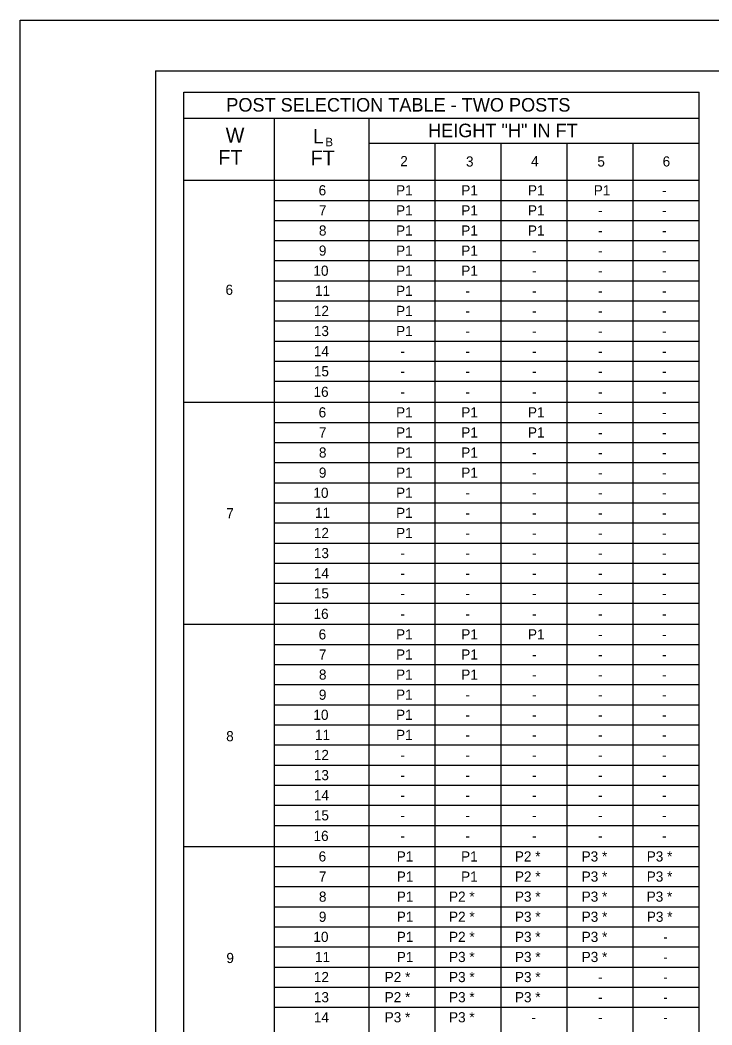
# Model space of a CAD drawing. Extents: x -2340 to 628, y -879 to 309.
# Drawn here: x -1117.4 to -912.9, y -581.5 to -284.6 of the extents above; entities that cross this region are included whole.
import ezdxf

# ---------------------------------------------------------------- set-up
doc = ezdxf.new("R2010")
doc.units = 0
for name, color, linetype in [('Level 1', 7, 'Continuous'), ('Level 2', 7, 'Continuous'), ('Level 30', 7, 'Continuous'), ('PLT-BNDY', 7, 'Continuous')]:
    doc.layers.add(name, color=color, linetype=linetype)

msp = doc.modelspace()

# ---------------------------------------------------------------- linework, layer by layer
at = {"layer": 'Level 1'}
for p, q in [((-1077.39, -299.56), (-291.39, -299.56)), ((-1077.39, -299.56), (-1077.39, -863.56)), ((-1069, -331.88), (-1069, -305.86)), ((-1069, -305.86), (-916.65, -305.86)), ((-916.65, -331.88), (-916.65, -305.86)), ((-1069, -313.54), (-916.65, -313.54)), ((-1042.2, -331.88), (-1042.2, -313.54)), ((-1014.19, -331.88), (-1014.19, -313.54)), ((-994.68, -331.88), (-994.68, -320.88)), ((-975.17, -331.88), (-975.17, -320.88)), ((-955.67, -331.88), (-955.67, -320.88)), ((-936.16, -331.88), (-936.16, -320.88)), ((-1069, -856.76), (-1069, -331.88)), ((-1069, -331.88), (-916.65, -331.88)), ((-975.85, -331.88), (-940.21, -331.88)), ((-916.65, -856.76), (-916.65, -331.88)), ((-975.85, -528.71), (-940.21, -528.71)), ((-940.21, -528.71), (-916.65, -528.71))]:
    msp.add_line(p, q, dxfattribs=at)
at = {"layer": 'Level 2'}
for p, q in [((-1014.19, -320.88), (-916.65, -320.88)), ((-1042.2, -856.76), (-1042.2, -331.88)), ((-1014.19, -856.76), (-1014.19, -331.88)), ((-994.68, -856.76), (-994.68, -331.88)), ((-975.17, -856.76), (-975.17, -331.88)), ((-955.67, -856.76), (-955.67, -331.88)), ((-936.16, -856.76), (-936.16, -331.88)), ((-1042.2, -337.82), (-916.65, -337.82)), ((-975.85, -337.82), (-940.21, -337.82)), ((-940.21, -337.82), (-916.65, -337.82)), ((-1042.2, -343.76), (-916.65, -343.76)), ((-975.85, -343.76), (-940.21, -343.76)), ((-940.21, -343.76), (-916.65, -343.76)), ((-1042.2, -349.7), (-916.65, -349.7)), ((-975.85, -349.7), (-940.21, -349.7)), ((-940.21, -349.7), (-916.65, -349.7)), ((-1042.2, -355.64), (-916.65, -355.64)), ((-975.85, -355.64), (-940.21, -355.64)), ((-940.21, -355.64), (-916.65, -355.64)), ((-1042.2, -361.58), (-916.65, -361.58)), ((-975.85, -361.58), (-940.21, -361.58)), ((-940.21, -361.58), (-916.65, -361.58)), ((-1042.2, -367.52), (-916.65, -367.52)), ((-975.85, -367.52), (-940.21, -367.52)), ((-940.21, -367.52), (-916.65, -367.52)), ((-1042.2, -373.46), (-916.65, -373.46)), ((-975.85, -373.46), (-940.21, -373.46)), ((-940.21, -373.46), (-916.65, -373.46)), ((-1042.2, -379.4), (-916.65, -379.4)), ((-975.85, -379.4), (-940.21, -379.4)), ((-940.21, -379.4), (-916.65, -379.4)), ((-1042.2, -385.34), (-916.65, -385.34)), ((-975.85, -385.34), (-940.21, -385.34)), ((-940.21, -385.34), (-916.65, -385.34)), ((-1042.2, -391.28), (-916.65, -391.28)), ((-975.85, -391.28), (-940.21, -391.28)), ((-940.21, -391.28), (-916.65, -391.28)), ((-1069, -397.49), (-916.65, -397.49)), ((-975.85, -397.49), (-940.21, -397.49)), ((-940.21, -397.49), (-916.65, -397.49)), ((-1042.2, -403.43), (-916.65, -403.43)), ((-975.85, -403.43), (-940.21, -403.43)), ((-940.21, -403.43), (-916.65, -403.43)), ((-1042.2, -409.37), (-916.65, -409.37)), ((-975.85, -409.37), (-940.21, -409.37)), ((-940.21, -409.37), (-916.65, -409.37)), ((-1042.2, -415.31), (-916.65, -415.31)), ((-975.85, -415.31), (-940.21, -415.31)), ((-940.21, -415.31), (-916.65, -415.31)), ((-1042.2, -421.25), (-916.65, -421.25)), ((-975.85, -421.25), (-940.21, -421.25)), ((-940.21, -421.25), (-916.65, -421.25)), ((-1042.2, -427.19), (-916.65, -427.19)), ((-975.85, -427.19), (-940.21, -427.19)), ((-940.21, -427.19), (-916.65, -427.19)), ((-1042.2, -433.13), (-916.65, -433.13)), ((-975.85, -433.13), (-940.21, -433.13)), ((-940.21, -433.13), (-916.65, -433.13)), ((-1042.2, -439.07), (-916.65, -439.07)), ((-975.85, -439.07), (-940.21, -439.07)), ((-940.21, -439.07), (-916.65, -439.07)), ((-1042.2, -445.01), (-916.65, -445.01)), ((-975.85, -445.01), (-940.21, -445.01)), ((-940.21, -445.01), (-916.65, -445.01)), ((-1042.2, -450.95), (-916.65, -450.95)), ((-975.85, -450.95), (-940.21, -450.95)), ((-1042.2, -456.89), (-916.65, -456.89)), ((-975.85, -456.89), (-940.21, -456.89)), ((-1069, -463.1), (-916.65, -463.1)), ((-975.85, -463.1), (-940.21, -463.1)), ((-1042.2, -469.04), (-916.65, -469.04)), ((-975.85, -469.04), (-940.21, -469.04)), ((-1042.2, -474.98), (-916.65, -474.98)), ((-975.85, -474.98), (-940.21, -474.98)), ((-1042.2, -480.92), (-916.65, -480.92)), ((-975.85, -480.92), (-940.21, -480.92)), ((-1042.2, -486.86), (-916.65, -486.86)), ((-975.85, -486.86), (-940.21, -486.86)), ((-1042.2, -492.8), (-916.65, -492.8)), ((-975.85, -492.8), (-940.21, -492.8)), ((-1042.2, -498.74), (-916.65, -498.74)), ((-1042.2, -504.68), (-916.65, -504.68)), ((-1042.2, -510.62), (-916.65, -510.62)), ((-1042.2, -516.56), (-916.65, -516.56)), ((-1042.2, -522.5), (-916.65, -522.5)), ((-1069, -528.71), (-916.65, -528.71)), ((-1042.2, -534.65), (-916.65, -534.65)), ((-1042.2, -540.59), (-916.65, -540.59)), ((-1042.2, -546.53), (-916.65, -546.53)), ((-1042.2, -552.47), (-916.65, -552.47)), ((-1042.2, -558.41), (-916.65, -558.41)), ((-1042.2, -564.35), (-916.65, -564.35)), ((-1042.2, -570.29), (-916.65, -570.29)), ((-1042.2, -576.23), (-916.65, -576.23))]:
    msp.add_line(p, q, dxfattribs=at)
at = {"layer": 'PLT-BNDY'}
msp.add_lwpolyline([(-1117.39, -284.56), (-276.39, -284.56), (-276.39, -878.56), (-1117.39, -878.56)], close=True, dxfattribs=at)

# ---------------------------------------------------------------- texts
at = {"layer": 'Level 1'}
for s, height, p in [('POST SELECTION TABLE - TWO POSTS', 4.003, (-1056.42, -311.6)), ('W', 4.37, (-1056.6, -320.74)), ('L', 4.3, (-1030.81, -321.01)), ('HEIGHT "H" IN FT', 4.003, (-996.77, -319.17)), ('B', 2.5, (-1027.1, -321.84)), ('FT', 4.375, (-1058.77, -327.3)), ('FT', 4.375, (-1031.5, -327.47)), ('2', 3, (-1005, -327.74)), ('3', 3, (-985.57, -327.84)), ('4', 3, (-966.32, -327.74)), ('5', 3, (-946.73, -327.84)), ('6', 3, (-927.43, -327.82))]:
    msp.add_text(s, height=height, dxfattribs=at).set_placement(p)
at = {"layer": 'Level 2'}
for s, p in [('7', (-1029.04, -342.29)), ('P1', (-1006.23, -342.29)), ('P1', (-986.96, -342.29)), ('P1', (-967.25, -342.29)), ('-', (-946.52, -342.29)), ('-', (-927.58, -342.29)), ('8', (-1029.04, -348.23)), ('P1', (-1006.23, -348.23)), ('P1', (-986.96, -348.23)), ('P1', (-967.25, -348.23)), ('-', (-946.52, -348.23)), ('-', (-927.58, -348.23)), ('9', (-1029.06, -354.17)), ('P1', (-1006.23, -354.17)), ('P1', (-986.96, -354.17)), ('-', (-965.98, -354.17)), ('-', (-946.52, -354.17)), ('-', (-927.58, -354.17)), ('10', (-1030.67, -360.11)), ('P1', (-1006.23, -360.11)), ('P1', (-986.96, -360.11)), ('-', (-965.98, -360.11)), ('-', (-946.52, -360.11)), ('-', (-927.58, -360.11)), ('11', (-1030.2, -366.05)), ('P1', (-1006.23, -366.05)), ('-', (-985.69, -366.05)), ('-', (-965.98, -366.05)), ('-', (-946.52, -366.05)), ('-', (-927.58, -366.05)), ('12', (-1030.54, -371.99)), ('P1', (-1006.23, -371.99)), ('-', (-985.69, -371.99)), ('-', (-965.98, -371.99)), ('-', (-946.52, -371.99)), ('-', (-927.58, -371.99)), ('13', (-1030.54, -377.93)), ('P1', (-1006.23, -377.93)), ('-', (-985.69, -377.93)), ('-', (-965.98, -377.93)), ('-', (-946.52, -377.93)), ('-', (-927.58, -377.93)), ('14', (-1030.54, -383.87)), ('-', (-1004.95, -383.87)), ('-', (-985.69, -383.87)), ('-', (-965.98, -383.87)), ('-', (-946.52, -383.87)), ('-', (-927.58, -383.87)), ('15', (-1030.54, -389.81)), ('-', (-1004.95, -389.81)), ('-', (-985.69, -389.81)), ('-', (-965.98, -389.81)), ('-', (-946.52, -389.81)), ('-', (-927.58, -389.81)), ('16', (-1030.63, -395.89)), ('-', (-1004.95, -395.89)), ('-', (-985.69, -395.89)), ('-', (-965.98, -395.89)), ('-', (-946.52, -395.89)), ('-', (-927.58, -395.89)), ('P1', (-1006.23, -401.96)), ('P1', (-986.96, -401.96)), ('P1', (-967.25, -401.96)), ('-', (-946.52, -401.96)), ('-', (-927.58, -401.96)), ('7', (-1029.04, -407.9)), ('P1', (-1006.23, -407.9)), ('P1', (-986.96, -407.9)), ('P1', (-967.25, -407.9)), ('-', (-946.52, -407.9)), ('-', (-927.58, -407.9)), ('8', (-1029.04, -413.84)), ('P1', (-1006.23, -413.84)), ('P1', (-986.96, -413.84)), ('-', (-965.98, -413.84)), ('-', (-946.52, -413.84)), ('-', (-927.58, -413.84)), ('9', (-1029.06, -419.78)), ('P1', (-1006.23, -419.78)), ('P1', (-986.96, -419.78)), ('-', (-965.98, -419.78)), ('-', (-946.52, -419.78)), ('-', (-927.58, -419.78)), ('10', (-1030.67, -425.72)), ('P1', (-1006.23, -425.72)), ('-', (-985.69, -425.72)), ('-', (-965.98, -425.72)), ('-', (-946.52, -425.72)), ('-', (-927.58, -425.72)), ('7', (-1056.43, -431.77)), ('11', (-1030.2, -431.66)), ('P1', (-1006.23, -431.66)), ('-', (-985.69, -431.66)), ('-', (-965.98, -431.66)), ('-', (-946.52, -431.66)), ('-', (-927.58, -431.66)), ('12', (-1030.54, -437.6)), ('P1', (-1006.23, -437.6)), ('-', (-985.69, -437.6)), ('-', (-965.98, -437.6)), ('-', (-946.52, -437.6)), ('-', (-927.58, -437.6)), ('13', (-1030.54, -443.54)), ('-', (-1004.95, -443.54)), ('-', (-985.69, -443.54)), ('-', (-965.98, -443.54)), ('-', (-946.52, -443.54)), ('-', (-927.58, -443.54)), ('14', (-1030.54, -449.48)), ('-', (-1004.95, -449.48)), ('-', (-985.69, -449.48)), ('-', (-965.98, -449.48)), ('-', (-946.52, -449.48)), ('-', (-927.58, -449.48)), ('15', (-1030.54, -455.42)), ('-', (-1004.95, -455.42)), ('-', (-985.69, -455.42)), ('-', (-965.98, -455.42)), ('-', (-946.52, -455.42)), ('-', (-927.58, -455.42)), ('16', (-1030.63, -461.5)), ('-', (-1004.95, -461.5)), ('-', (-985.69, -461.5)), ('-', (-965.98, -461.5)), ('-', (-946.52, -461.5)), ('-', (-927.58, -461.5)), ('P1', (-1006.23, -467.57)), ('P1', (-986.96, -467.57)), ('P1', (-967.25, -467.57)), ('-', (-946.52, -467.57)), ('-', (-927.58, -467.57)), ('7', (-1029.04, -473.51)), ('P1', (-1006.23, -473.51)), ('P1', (-986.96, -473.51)), ('-', (-965.98, -473.51)), ('-', (-946.52, -473.51)), ('-', (-927.58, -473.51)), ('8', (-1029.04, -479.45)), ('P1', (-1006.23, -479.45)), ('P1', (-986.96, -479.45)), ('-', (-965.98, -479.45)), ('-', (-946.52, -479.45)), ('-', (-927.58, -479.45)), ('9', (-1029.06, -485.39)), ('P1', (-1006.23, -485.39)), ('-', (-985.69, -485.39)), ('-', (-965.98, -485.39)), ('-', (-946.52, -485.39)), ('-', (-927.58, -485.39)), ('10', (-1030.67, -491.33)), ('P1', (-1006.23, -491.33)), ('-', (-985.69, -491.33)), ('-', (-965.98, -491.33)), ('-', (-946.52, -491.33)), ('-', (-927.58, -491.33)), ('8', (-1056.46, -497.64)), ('11', (-1030.2, -497.27)), ('P1', (-1006.23, -497.27)), ('-', (-985.69, -497.27)), ('-', (-965.98, -497.27)), ('-', (-946.52, -497.27)), ('-', (-927.58, -497.27)), ('12', (-1030.54, -503.21)), ('-', (-1004.95, -503.21)), ('-', (-985.69, -503.21)), ('-', (-965.98, -503.21)), ('-', (-946.52, -503.21)), ('-', (-927.58, -503.21)), ('13', (-1030.54, -509.15)), ('-', (-1004.95, -509.15)), ('-', (-985.69, -509.15)), ('-', (-965.98, -509.15)), ('-', (-946.52, -509.15)), ('-', (-927.58, -509.15)), ('14', (-1030.54, -515.09)), ('-', (-1004.95, -515.09)), ('-', (-985.69, -515.09)), ('-', (-965.98, -515.09)), ('-', (-946.52, -515.09)), ('-', (-927.58, -515.09)), ('15', (-1030.54, -521.03)), ('-', (-1004.95, -521.03)), ('-', (-985.69, -521.03)), ('-', (-965.98, -521.03)), ('-', (-946.52, -521.03)), ('-', (-927.58, -521.03)), ('16', (-1030.63, -527.11)), ('-', (-1004.95, -527.11)), ('-', (-985.69, -527.11)), ('-', (-965.98, -527.11)), ('-', (-946.52, -527.11)), ('-', (-927.58, -527.11)), ('P1', (-1006.04, -533.18)), ('P1', (-987.01, -533.18)), ('P2 *', (-971.12, -533.18)), ('P3 *', (-951.38, -533.18)), ('P3 *', (-932.13, -533.18)), ('7', (-1029.04, -539.12)), ('P1', (-1006.02, -539.12)), ('P1', (-987.01, -539.12)), ('P2 *', (-971.1, -539.12)), ('P3 *', (-951.36, -539.12)), ('P3 *', (-932.13, -539.12)), ('8', (-1029.04, -545.06)), ('P1', (-1006.02, -545.06)), ('P2 *', (-990.58, -545.06)), ('P3 *', (-971.1, -545.06)), ('P3 *', (-951.36, -545.06)), ('P3 *', (-932.15, -545.06)), ('9', (-1029.06, -551)), ('P1', (-1006.02, -551)), ('P2 *', (-990.58, -551)), ('P3 *', (-971.1, -551)), ('P3 *', (-951.36, -551)), ('P3 *', (-932.1, -551)), ('10', (-1030.67, -556.94)), ('P1', (-1006.02, -556.94)), ('P2 *', (-990.58, -556.94)), ('P3 *', (-971.1, -556.94)), ('P3 *', (-951.36, -556.94)), ('-', (-927.25, -556.94)), ('9', (-1056.4, -563.18)), ('11', (-1030.2, -562.88)), ('P1', (-1006.02, -562.88)), ('P3 *', (-990.58, -562.88)), ('P3 *', (-971.1, -562.88)), ('P3 *', (-951.36, -562.88)), ('-', (-927.25, -562.88)), ('12', (-1030.54, -568.82)), ('P2 *', (-1009.6, -568.82)), ('P3 *', (-990.58, -568.82)), ('P3 *', (-971.1, -568.82)), ('-', (-946.51, -568.82)), ('-', (-927.25, -568.82)), ('13', (-1030.54, -574.76)), ('P2 *', (-1009.6, -574.76)), ('P3 *', (-990.58, -574.76)), ('P3 *', (-971.1, -574.76)), ('-', (-946.51, -574.76)), ('-', (-927.25, -574.76)), ('14', (-1030.54, -580.7)), ('P3 *', (-1009.6, -580.7)), ('P3 *', (-990.58, -580.7)), ('-', (-966.25, -580.7)), ('-', (-946.51, -580.7)), ('-', (-927.25, -580.7))]:
    msp.add_text(s, height=3, dxfattribs=at).set_placement(p)
at = {"layer": 'Level 30'}
for s, p in [('6', (-1029.13, -336.35)), ('P1', (-1006.23, -336.35)), ('P1', (-986.96, -336.35)), ('P1', (-967.25, -336.35)), ('P1', (-947.8, -336.35)), ('-', (-927.58, -336.35)), ('6', (-1056.66, -365.75)), ('6', (-1029.13, -401.96)), ('6', (-1029.13, -467.57)), ('6', (-1029.13, -533.18))]:
    msp.add_text(s, height=3, dxfattribs=at).set_placement(p)

doc.saveas('drawing.dxf')
